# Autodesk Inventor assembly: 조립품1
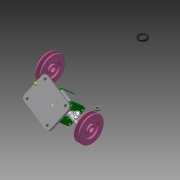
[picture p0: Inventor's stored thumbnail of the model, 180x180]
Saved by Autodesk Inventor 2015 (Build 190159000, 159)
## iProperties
Created: 2020-11
Part Number: 조립품1
Document SubType Name: Assembly
Designer: pc-04
Author: pc-04
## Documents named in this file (10)
- C:\Users\pc-04\Desktop\701106V1056\조립품1.iam
- C:\Users\pc-04\Desktop\701106V1056\본체.ipt
- C:\Users\pc-04\Desktop\701106V1056\V-벨트풀리.ipt
- C:\Users\pc-04\Desktop\701106V1056\너트 M10x1.ipt
- C:\Users\pc-04\Desktop\701106V1056\베어링 6004.ipt
- C:\Users\pc-04\Desktop\701106V1056\볼트 M4.ipt
- C:\Users\pc-04\Desktop\701106V1056\오일 실 17 30 5.ipt
- C:\Users\pc-04\Desktop\701106V1056\축.ipt
- C:\Users\pc-04\Desktop\701106V1056\커버.ipt
- C:\Users\pc-04\Desktop\701106V1056\키 5 x 5 x 12.ipt
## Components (2 placed, 1 different names)
1. V-벨트풀리:1
2. V-벨트풀리:2
